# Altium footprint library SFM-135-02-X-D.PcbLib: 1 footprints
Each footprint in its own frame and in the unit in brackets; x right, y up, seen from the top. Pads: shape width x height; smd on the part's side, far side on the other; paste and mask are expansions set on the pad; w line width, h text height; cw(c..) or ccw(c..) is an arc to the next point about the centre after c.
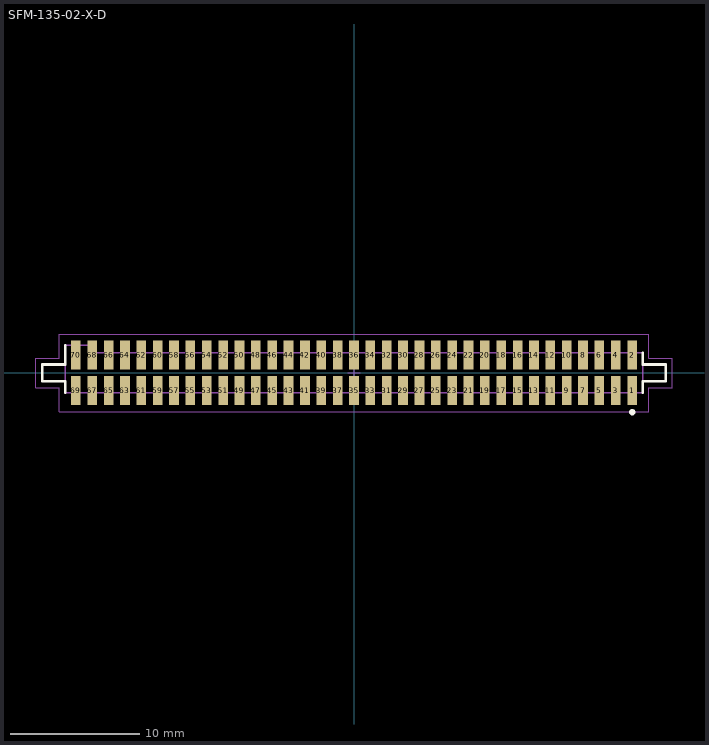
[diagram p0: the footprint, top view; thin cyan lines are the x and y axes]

## SFM-135-02-X-D [mm] "1.27mm pitch, 70 pin, socket strip; SMT"
height 4.57
pads (70):
  rect 0.75x2.25 smd mask+0: 1(21.59,-1.375) 2(21.59,1.375) 3(20.32,-1.375) 4(20.32,1.375) 5(19.05,-1.375) 6(19.05,1.375) 7(17.78,-1.375) 8(17.78,1.375) 9(16.51,-1.375) 10(16.51,1.375) 11(15.24,-1.375) 12(15.24,1.375) 13(13.97,-1.375) 14(13.97,1.375) 15(12.7,-1.375) 16(12.7,1.375) 17(11.43,-1.375) 18(11.43,1.375) 19(10.16,-1.375) 20(10.16,1.375) 21(8.89,-1.375) 22(8.89,1.375) 23(7.62,-1.375) 24(7.62,1.375) 25(6.35,-1.375) 26(6.35,1.375) 27(5.08,-1.375) 28(5.08,1.375) 29(3.81,-1.375) 30(3.81,1.375) 31(2.54,-1.375) 32(2.54,1.375) 33(1.27,-1.375) 34(1.27,1.375) 35(0,-1.375) 36(0,1.375) 37(-1.27,-1.375) 38(-1.27,1.375) 39(-2.54,-1.375) 40(-2.54,1.375) 41(-3.81,-1.375) 42(-3.81,1.375) 43(-5.08,-1.375) 44(-5.08,1.375) 45(-6.35,-1.375) 46(-6.35,1.375) 47(-7.62,-1.375) 48(-7.62,1.375) 49(-8.89,-1.375) 50(-8.89,1.375) 51(-10.16,-1.375) 52(-10.16,1.375) 53(-11.43,-1.375) 54(-11.43,1.375) 55(-12.7,-1.375) 56(-12.7,1.375) 57(-13.97,-1.375) 58(-13.97,1.375) 59(-15.24,-1.375) 60(-15.24,1.375) 61(-16.51,-1.375) 62(-16.51,1.375) 63(-17.78,-1.375) 64(-17.78,1.375) 65(-19.05,-1.375) 66(-19.05,1.375) 67(-20.32,-1.375) 68(-20.32,1.375) 69(-21.59,-1.375) 70(-21.59,1.375)
Top Overlay:
  circle w0.25: c21.6,-3.05 r0.125
  lines w0.2: -22.4,-1.55 -22.4,-0.65 -24.2,-0.65 -24.2,0.65 -22.4,0.65 -22.4,2.15 ; 22.4,-1.55 22.4,-0.65 24.2,-0.65 24.2,0.65 22.4,0.65 22.4,1.55
Mechanical 12:
  lines w0.001: -24.2,-0.65 -22.4,-0.65 -22.4,-1.55 22.4,-1.55 22.4,-0.65 24.2,-0.65 24.2,0.65 22.4,0.65 22.4,1.55 -20.35,1.55 -20.35,2.15 -22.4,2.15 -22.4,0.65 -24.2,0.65 -24.2,-0.65
Mechanical 13:
  lines w0.1: -22.4,-0.65 -22.4,-1.55 22.4,-1.55 22.4,-0.65 ; -22.4,-0.65 -24.2,-0.65 -24.2,0.65 -22.4,0.65 ; -22.4,-0.65 -22.4,0.65 ; -22.4,0.65 -22.4,2.15 -20.35,2.15 -20.35,1.55 22.4,1.55 22.4,0.65 ; 22.4,-0.65 24.2,-0.65 24.2,0.65 22.4,0.65 ; 22.4,-0.65 22.4,0.65
  text ".Designator" at 0.127,-0.127 h1.52
Mechanical 15:
  lines w0.05: -0.5,0 0.5,0 ; 0,-0.5 0,0.5 ; -24.7,-1.15 -24.7,1.15 -22.9,1.15 -22.9,3 22.9,3 22.9,1.15 24.7,1.15 24.7,-1.15 22.9,-1.15 22.9,-3 -22.9,-3 -22.9,-1.15 -24.7,-1.15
